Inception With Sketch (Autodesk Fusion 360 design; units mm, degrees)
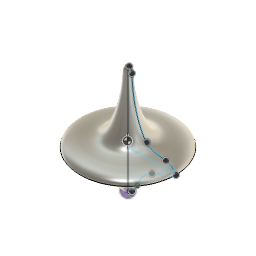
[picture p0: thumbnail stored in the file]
part number: 2025-09-25-20-54-50-305
part number: 2025-09-25-20-56-10-703
canvas "Canvas1"
sketch "Sketch1" plane through (0, 0, 0) normal (0, 1, 0) x axis (1, 0, 0)
  curve K1 (0.5, -40.5) -> (0.5, 0)
  line L1 (0, -40.5) -> (0.5, -40.5)
  curve K2 (1.1668, -42.2128) -> (1.7712, -35.2766)
  curve K3 (-2.5, -40.5) -> (3.5, -40.5)
  line L2 (0, -14) -> (18, -14)
  line L3 (0, -40.5) -> (0, -14)
  line L4 (0, 0) -> (0.5, 0)
  line L5 (0, -14) -> (0, 0)
  point P9 (1.469, -38.7447)
  point P10 (0.5, -40.5)
  point P6 (18, -14)
  point P16 (18, -14)
  point P1 (0, 0)
  point P18 (0, 0)
  horizontal L1
  midpoint P9 K2
  midpoint P10 K3
  coincident P6 P16
  horizontal L2
  perpendicular L1 L3
  coincident P1 P18
  horizontal L4
  perpendicular L4 L5
revolve "Revolve6" sketch "Sketch1" AlongAngle 360
shell "Shell2" innerThickness 1
revolve "Revolve7" sketch "Sketch1" AlongAngle 360
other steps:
create_component "CreateComponent1"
